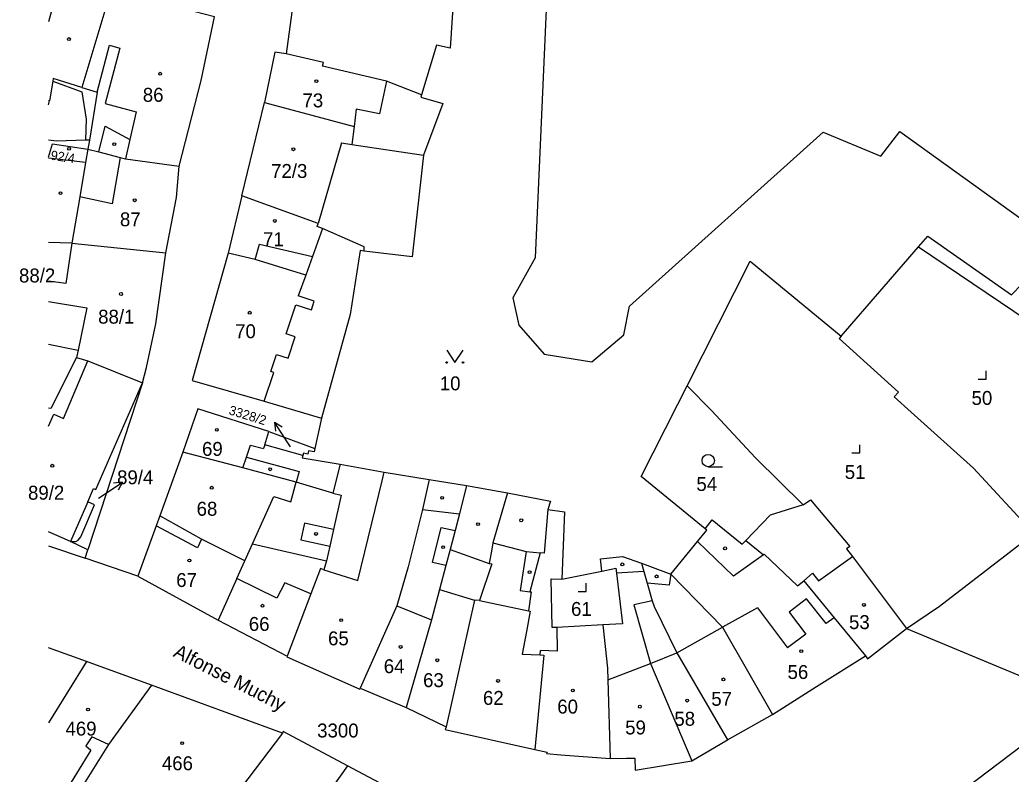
# Model space of a CAD drawing. Extents: x -600849 to -599899, y -1204328 to -1203436.
# Drawn here: x -600846.7 to -600725.7, y -1204120.9 to -1204028.8 of the extents above; entities that cross this region are included whole.
import ezdxf

# ---------------------------------------------------------------- set-up
doc = ezdxf.new("R2010")
doc.units = 0
for name, color, linetype in [('Vrstva 1', 7, 'Continuous'), ('Vrstva 2', 7, 'Continuous'), ('Vrstva 3', 7, 'Continuous'), ('Vrstva 4', 7, 'Continuous'), ('Vrstva 5', 7, 'Continuous'), ('Vrstva 7', 7, 'Continuous')]:
    doc.layers.add(name, color=color, linetype=linetype)

msp = doc.modelspace()

# ---------------------------------------------------------------- linework, layer by layer
at = {"layer": 'Vrstva 1'}
for p, q in [((-600811.67, -1204014.98), (-600814.17, -1204032.93)), ((-600835.54, -1204025.11), (-600839.12, -1204037.04)), ((-600819.57, -1204050.27), (-600816.82, -1204038.87)), ((-600838.36, -1204044.57), (-600838.64, -1204046.19)), ((-600838.64, -1204046.19), (-600843.16, -1204045.67)), ((-600819.57, -1204050.27), (-600821.24, -1204057.28)), ((-600840.32, -1204056.04), (-600841.05, -1204060.99)), ((-600840.32, -1204056.04), (-600828.84, -1204057.25)), ((-600746.41, -1204067.39), (-600736.97, -1204056.52)), ((-600843.16, -1204068.39), (-600839.53, -1204069.11)), ((-600839.53, -1204069.11), (-600839.75, -1204070.02)), ((-600831.7, -1204073.1), (-600838.37, -1204093.5)), ((-600765.22, -1204073.49), (-600762.25, -1204076.47)), ((-600809.83, -1204077.4), (-600810.67, -1204081.12)), ((-600816.28, -1204079.06), (-600810.67, -1204081.12)), ((-600826.77, -1204081.58), (-600829.59, -1204089.34)), ((-600807.55, -1204083.04), (-600808.46, -1204086.56)), ((-600796.7, -1204084.9), (-600792.16, -1204085.62)), ((-600792.16, -1204085.62), (-600787.16, -1204086.53)), ((-600782.21, -1204088.57), (-600780.17, -1204088.84)), ((-600751.07, -1204087.99), (-600755.08, -1204089.24)), ((-600780.17, -1204088.84), (-600780.52, -1204097.07)), ((-600755.08, -1204089.24), (-600758.04, -1204092.34)), ((-600758.04, -1204092.34), (-600755.91, -1204094.11)), ((-600843.16, -1204093.01), (-600838.7, -1204094.53)), ((-600838.37, -1204093.5), (-600840.47, -1204092.47)), ((-600838.7, -1204094.53), (-600838.37, -1204093.5)), ((-600832.27, -1204096.72), (-600838.7, -1204094.53)), ((-600770.8, -1204095.14), (-600767.2, -1204096.46)), ((-600832.27, -1204096.72), (-600822.47, -1204102.08)), ((-600820.17, -1204096.99), (-600822.47, -1204102.08)), ((-600780.52, -1204097.07), (-600775.64, -1204096.09)), ((-600811.15, -1204098.86), (-600814.03, -1204106.46)), ((-600784.37, -1204100.98), (-600784.83, -1204103.48)), ((-600822.47, -1204102.08), (-600814.03, -1204106.46)), ((-600775.51, -1204102.65), (-600781.14, -1204102.98)), ((-600738.45, -1204103.11), (-600717.23, -1204111.96)), ((-600838.55, -1204107.14), (-600843.16, -1204105.44)), ((-600766.49, -1204106.06), (-600760.28, -1204116.67)), ((-600838.55, -1204107.14), (-600843.16, -1204114.61)), ((-600830.6, -1204110.03), (-600838.55, -1204107.14)), ((-600769.68, -1204107.36), (-600764.65, -1204119.27)), ((-600830.6, -1204110.03), (-600835.83, -1204117.26)), ((-600814.59, -1204115.86), (-600830.6, -1204110.03)), ((-600805.11, -1204110.37), (-600799.52, -1204112.73)), ((-600799.52, -1204112.73), (-600794.63, -1204115.11)), ((-600747.51, -1204134.92), (-600717.23, -1204111.96)), ((-600760.28, -1204116.67), (-600754.81, -1204113.59)), ((-600814.59, -1204115.86), (-600823.85, -1204128.03)), ((-600764.65, -1204119.27), (-600760.28, -1204116.67)), ((-600799.24, -1204123.79), (-600806.67, -1204119.86))]:
    msp.add_line(p, q, dxfattribs=at)
for points in [[(-600781.84, -1203949), (-600781.01, -1203959.65), (-600780.83, -1203983.13), (-600781.28, -1203997.12), (-600781.6, -1204007.31), (-600784.23, -1204015.61), (-600782.99, -1204026.27), (-600782.43, -1204027.52), (-600783.78, -1204057.86), (-600786.51, -1204062.72)], [(-600793.25, -1204018.6), (-600794.15, -1204032.23), (-600795.8, -1204031.86), (-600797.64, -1204037.95)], [(-600827.23, -1204046.67), (-600824.53, -1204036.21), (-600822.91, -1204028.4), (-600835.54, -1204025.11)], [(-600814.17, -1204032.93), (-600815.56, -1204032.73), (-600816.82, -1204038.87)], [(-600797.64, -1204037.95), (-600801.93, -1204036.26), (-600809.72, -1204034.45), (-600809.61, -1204033.99), (-600814.17, -1204032.93)], [(-600839.12, -1204037.04), (-600842.61, -1204035.96), (-600842.66, -1204036.27), (-600843.06, -1204038.67), (-600843.16, -1204038.66)], [(-600839.12, -1204037.04), (-600837.23, -1204037.63), (-600838.18, -1204043.46), (-600838.36, -1204044.57)], [(-600816.82, -1204038.87), (-600805.87, -1204041.79), (-600806.13, -1204043.99), (-600797.38, -1204045.31)], [(-600797.64, -1204037.95), (-600797.72, -1204038.22), (-600795.05, -1204039), (-600797.38, -1204045.31)], [(-600786.51, -1204062.72), (-600785.78, -1204066.08), (-600782.69, -1204069.61), (-600776.86, -1204070.56), (-600772.94, -1204067.26), (-600772.25, -1204063.73), (-600748.62, -1204042.5), (-600741.59, -1204045.45), (-600739.25, -1204042.4), (-600717.66, -1204057.97), (-600709.47, -1204069.87)], [(-600843.16, -1204045.56), (-600842.69, -1204043.92), (-600838.36, -1204044.57)], [(-600838.36, -1204044.57), (-600837.03, -1204044.91), (-600834.42, -1204045.58), (-600833.78, -1204045.74), (-600827.23, -1204046.67)], [(-600838.64, -1204046.19), (-600839.34, -1204050.38), (-600840.32, -1204056.04)], [(-600797.38, -1204045.31), (-600798.79, -1204057.72), (-600804.66, -1204057.01)], [(-600828.84, -1204057.25), (-600827.56, -1204050.48), (-600827.23, -1204046.67)], [(-600809.73, -1204054.28), (-600810.38, -1204054), (-600810.27, -1204053.64), (-600819.57, -1204050.27)], [(-600809.73, -1204054.28), (-600810.96, -1204057.67), (-600811.78, -1204059.95), (-600817.93, -1204058.05), (-600821.24, -1204057.28)], [(-600804.66, -1204057.01), (-600804.63, -1204056.5), (-600809.73, -1204054.28)], [(-600840.32, -1204056.04), (-600843.16, -1204055.97)], [(-600736.97, -1204056.52), (-600735.85, -1204055.2), (-600725.62, -1204062.37), (-600724.36, -1204061.07), (-600721.14, -1204063.73), (-600719.04, -1204060.78), (-600709.47, -1204069.87)], [(-600831.7, -1204073.1), (-600831.2, -1204071.25), (-600830.06, -1204065.9), (-600828.84, -1204057.25)], [(-600821.24, -1204057.28), (-600825.65, -1204072.8), (-600816.84, -1204075.36), (-600809.83, -1204077.4)], [(-600804.66, -1204057.01), (-600805.13, -1204056.95), (-600806.34, -1204064.76), (-600809.83, -1204077.4)], [(-600736.97, -1204056.52), (-600712.07, -1204073.32), (-600705.63, -1204077.44)], [(-600765.22, -1204073.49), (-600757.51, -1204058.26), (-600746.41, -1204067.39)], [(-600841.05, -1204060.99), (-600843.16, -1204060.7)], [(-600843.16, -1204063.16), (-600838.51, -1204063.96), (-600839.53, -1204069.11)], [(-600746.41, -1204067.39), (-600746.66, -1204067.68), (-600739.43, -1204074.26), (-600739.95, -1204074.83), (-600737.87, -1204076.7)], [(-600839.75, -1204070.02), (-600842.89, -1204076.25), (-600843.16, -1204076.19)], [(-600839.75, -1204070.02), (-600838.38, -1204070.41), (-600831.7, -1204073.1)], [(-600840.47, -1204092.47), (-600839.82, -1204092.47), (-600839.54, -1204092.32), (-600839.23, -1204091.91), (-600837.55, -1204087.98), (-600838.38, -1204087.62), (-600837.68, -1204086.01), (-600837.4, -1204086.14), (-600831.7, -1204073.1)], [(-600763.02, -1204090.93), (-600770.83, -1204084.53), (-600766.38, -1204075.79), (-600765.22, -1204073.49)], [(-600816.28, -1204079.06), (-600824.94, -1204076.29), (-600826.77, -1204081.58)], [(-600762.25, -1204076.47), (-600756.88, -1204082.25), (-600751.07, -1204087.99)], [(-600737.87, -1204076.7), (-600730.26, -1204083.54), (-600722.9, -1204091.5)], [(-600812.13, -1204081.97), (-600816.77, -1204080.69), (-600816.28, -1204079.06)], [(-600810.67, -1204081.12), (-600810.76, -1204081.51), (-600811.42, -1204081.42), (-600811.5, -1204081.81), (-600812.06, -1204081.68), (-600812.13, -1204081.97)], [(-600808.46, -1204086.56), (-600812.95, -1204085.24), (-600819.47, -1204083.47), (-600826.77, -1204081.58)], [(-600812.13, -1204081.97), (-600812.21, -1204082.26), (-600807.55, -1204083.04)], [(-600807.55, -1204083.04), (-600802.2, -1204084.02), (-600796.7, -1204084.9)], [(-600796.7, -1204084.9), (-600797.54, -1204088.56), (-600799.26, -1204095.58), (-600800.66, -1204100.33), (-600805.11, -1204110.37)], [(-600792.16, -1204085.62), (-600793.01, -1204089.11), (-600793.54, -1204091.14), (-600794.15, -1204093.45), (-600794.67, -1204095.42), (-600795.44, -1204098.35), (-600796.41, -1204102.02), (-600799.52, -1204112.73)], [(-600808.46, -1204086.56), (-600807.45, -1204086.83), (-600808.39, -1204091.01), (-600808.84, -1204093.04), (-600809.23, -1204094.82), (-600809.56, -1204095.94), (-600809.97, -1204095.77), (-600811.15, -1204098.86)], [(-600787.16, -1204086.53), (-600788.93, -1204092.64), (-600789.07, -1204093.43)], [(-600787.16, -1204086.53), (-600781.89, -1204087.56), (-600782.21, -1204088.57)], [(-600751.07, -1204087.99), (-600750.18, -1204087.39), (-600745.34, -1204093.08), (-600745.77, -1204093.37), (-600745.05, -1204094.32), (-600738.45, -1204103.11)], [(-600782.21, -1204088.57), (-600782.65, -1204093.88), (-600783.17, -1204093.84), (-600784.4, -1204098.6), (-600784.27, -1204098.61), (-600784.59, -1204100.93), (-600784.37, -1204100.98)], [(-600829.59, -1204089.34), (-600830.03, -1204090.55), (-600832.27, -1204096.72)], [(-600820.17, -1204096.99), (-600819.19, -1204094.83), (-600824.48, -1204092.21), (-600829.59, -1204089.34)], [(-600763.02, -1204090.93), (-600762.16, -1204089.81), (-600758.5, -1204092.82), (-600758.04, -1204092.34)], [(-600767.2, -1204096.46), (-600763.94, -1204092.48), (-600762.81, -1204091.1), (-600763.02, -1204090.93)], [(-600840.47, -1204092.47), (-600843.16, -1204091.3)], [(-600738.45, -1204103.11), (-600734.4, -1204100.35), (-600722.9, -1204091.5)], [(-600789.07, -1204093.43), (-600789.39, -1204095.18), (-600789.04, -1204095.2), (-600790.58, -1204099.66), (-600791.18, -1204099.62), (-600794.63, -1204115.11)], [(-600775.64, -1204096.09), (-600775.81, -1204094.58), (-600773.1, -1204094.3), (-600770.8, -1204095.14)], [(-600755.91, -1204094.11), (-600755.8, -1204094.01), (-600751.73, -1204097.89), (-600750.99, -1204097.26)], [(-600775.64, -1204096.09), (-600773.93, -1204095.74), (-600773.86, -1204096.35), (-600773.11, -1204102.51), (-600775.51, -1204102.65)], [(-600770.8, -1204095.14), (-600770.5, -1204096.15), (-600770.09, -1204097.58), (-600769.47, -1204099.71)], [(-600811.15, -1204098.86), (-600814.32, -1204097.52), (-600815.28, -1204099.41), (-600820.17, -1204096.99)], [(-600781.14, -1204102.98), (-600781.69, -1204102.96), (-600781.81, -1204097.04), (-600780.52, -1204097.07)], [(-600767.2, -1204096.46), (-600760.92, -1204102.94), (-600754.81, -1204113.59)], [(-600750.99, -1204097.26), (-600747.27, -1204101.78), (-600743.44, -1204106.44)], [(-600769.47, -1204099.71), (-600771.71, -1204100.22), (-600769.68, -1204107.36)], [(-600769.47, -1204099.71), (-600769.26, -1204100.41), (-600766.49, -1204106.06)], [(-600775.51, -1204102.65), (-600774.95, -1204107.93), (-600774.91, -1204109.38), (-600774.61, -1204118.96)], [(-600743.44, -1204106.44), (-600743.2, -1204106.79), (-600738.45, -1204103.11)], [(-600784.83, -1204103.48), (-600785.34, -1204106.23), (-600783.16, -1204106.33), (-600782.71, -1204106.35), (-600783.82, -1204117.88)], [(-600814.03, -1204106.46), (-600814.06, -1204106.55), (-600805.17, -1204110.51), (-600805.11, -1204110.37)], [(-600754.81, -1204113.59), (-600749.41, -1204110.18), (-600743.44, -1204106.44)], [(-600794.63, -1204115.11), (-600794.76, -1204115.42), (-600783.82, -1204117.88)], [(-600806.67, -1204119.86), (-600814.51, -1204115.67), (-600814.59, -1204115.86)], [(-600835.83, -1204117.26), (-600838.68, -1204121.81), (-600840.92, -1204125.39)], [(-600783.82, -1204117.88), (-600782.32, -1204118.2), (-600782.38, -1204118.36), (-600780.63, -1204118.51), (-600774.61, -1204118.96)], [(-600774.61, -1204118.96), (-600772.61, -1204118.93), (-600771.6, -1204118.91), (-600771.57, -1204120.39), (-600764.65, -1204119.27)], [(-600806.67, -1204119.86), (-600812.52, -1204128.13), (-600816.88, -1204134.04), (-600819.75, -1204137.27), (-600824.52, -1204142.43), (-600829.08, -1204147.45), (-600833.81, -1204152)]]:
    msp.add_lwpolyline(points, dxfattribs=at)
at = {"layer": 'Vrstva 3'}
for p, q in [((-600728.7, -1204072.64), (-600728.7, -1204071.64)), ((-600729.7, -1204072.64), (-600728.7, -1204072.64)), ((-600744.12, -1204081.67), (-600744.12, -1204080.67)), ((-600745.12, -1204081.67), (-600744.12, -1204081.67)), ((-600762.64, -1204083.35), (-600760.89, -1204083.35)), ((-600777.53, -1204098.56), (-600777.53, -1204097.56)), ((-600778.53, -1204098.56), (-600777.53, -1204098.56))]:
    msp.add_line(p, q, dxfattribs=at)
msp.add_lwpolyline([(-600794.57, -1204069.12), (-600793.57, -1204070.62), (-600792.57, -1204069.12)], dxfattribs=at)
for centre, radius in [((-600794.57, -1204070.62), 0.1), ((-600792.57, -1204070.62), 0.1), ((-600762.64, -1204082.6), 0.75)]:
    msp.add_circle(centre, radius, dxfattribs=at)
at = {"layer": 'Vrstva 4'}
for p, q in [((-600841.6, -1204023.22), (-600843.16, -1204029.05)), ((-600837.23, -1204037.63), (-600835.72, -1204031.89)), ((-600834.48, -1204032.24), (-600836.24, -1204039)), ((-600835.72, -1204031.89), (-600834.48, -1204032.24)), ((-600842.66, -1204036.27), (-600839.1, -1204037.56)), ((-600801.93, -1204036.26), (-600802.77, -1204040.27)), ((-600839.1, -1204037.56), (-600838.58, -1204040.9)), ((-600843.16, -1204039.15), (-600843.06, -1204038.67)), ((-600836.24, -1204039), (-600832.47, -1204040.02)), ((-600832.47, -1204040.02), (-600833.24, -1204043.4)), ((-600805.61, -1204039.68), (-600805.87, -1204041.79)), ((-600802.77, -1204040.27), (-600805.61, -1204039.68)), ((-600838.58, -1204040.9), (-600838.67, -1204043.48)), ((-600837.03, -1204044.91), (-600836.26, -1204041.76)), ((-600836.26, -1204041.76), (-600833.24, -1204043.4)), ((-600842.18, -1204043.61), (-600843.16, -1204043.47)), ((-600838.67, -1204043.48), (-600842.18, -1204043.61)), ((-600838.18, -1204043.46), (-600838.67, -1204043.48)), ((-600833.24, -1204043.4), (-600833.78, -1204045.74)), ((-600807.39, -1204043.8), (-600810.27, -1204053.64)), ((-600807.39, -1204043.8), (-600806.13, -1204043.99)), ((-600834.42, -1204045.58), (-600835.39, -1204051.25)), ((-600835.39, -1204051.25), (-600839.34, -1204050.38)), ((-600817.93, -1204058.05), (-600817.4, -1204056.18)), ((-600817.4, -1204056.18), (-600810.96, -1204057.67)), ((-600811.78, -1204059.95), (-600812.7, -1204062.5)), ((-600810.74, -1204063.13), (-600812.7, -1204062.5)), ((-600811.08, -1204064.19), (-600810.74, -1204063.13)), ((-600814.17, -1204067.13), (-600812.98, -1204063.57)), ((-600812.98, -1204063.57), (-600811.08, -1204064.19)), ((-600813.05, -1204067.5), (-600814.17, -1204067.13)), ((-600813.92, -1204070.1), (-600813.05, -1204067.5)), ((-600841.35, -1204077.46), (-600838.38, -1204070.41)), ((-600816.04, -1204071.73), (-600815.34, -1204069.63)), ((-600815.34, -1204069.63), (-600813.92, -1204070.1)), ((-600815.67, -1204071.85), (-600816.04, -1204071.73)), ((-600816.84, -1204075.36), (-600815.67, -1204071.85)), ((-600843.16, -1204078.38), (-600842.51, -1204076.94)), ((-600842.51, -1204076.94), (-600841.35, -1204077.46)), ((-600819.01, -1204082.16), (-600818.51, -1204080.73)), ((-600818.51, -1204080.73), (-600816.91, -1204081.14)), ((-600816.77, -1204080.69), (-600816.91, -1204081.14)), ((-600819.47, -1204083.47), (-600819.01, -1204082.16)), ((-600819.01, -1204082.16), (-600812.58, -1204083.94)), ((-600812.58, -1204083.94), (-600812.95, -1204085.24)), ((-600805.43, -1204097.23), (-600802.45, -1204085.08)), ((-600802.45, -1204085.08), (-600802.2, -1204084.02)), ((-600813.6, -1204087.64), (-600812.95, -1204085.24)), ((-600818.26, -1204092.77), (-600815.66, -1204086.99)), ((-600815.66, -1204086.99), (-600813.6, -1204087.64)), ((-600838.38, -1204087.62), (-600840.47, -1204092.47)), ((-600797.54, -1204088.56), (-600793.01, -1204089.11)), ((-600825, -1204093.24), (-600830.03, -1204090.55)), ((-600811.91, -1204090.22), (-600812.36, -1204092.26)), ((-600808.39, -1204091.01), (-600811.91, -1204090.22)), ((-600796.29, -1204095.04), (-600795.24, -1204090.76)), ((-600795.24, -1204090.76), (-600793.54, -1204091.14)), ((-600824.48, -1204092.21), (-600825, -1204093.24)), ((-600812.36, -1204092.26), (-600808.84, -1204093.04)), ((-600819.19, -1204094.83), (-600818.26, -1204092.77)), ((-600818.26, -1204092.77), (-600809.23, -1204094.82)), ((-600794.15, -1204093.45), (-600789.39, -1204095.18)), ((-600788.93, -1204092.64), (-600784.88, -1204093.71)), ((-600763.94, -1204092.48), (-600759.54, -1204096.71)), ((-600784.88, -1204093.71), (-600785.6, -1204098.47)), ((-600784.88, -1204093.71), (-600783.17, -1204093.84)), ((-600755.91, -1204094.11), (-600759.54, -1204096.71)), ((-600749.18, -1204097.26), (-600745.05, -1204094.32)), ((-600809.56, -1204095.94), (-600805.43, -1204097.23)), ((-600794.67, -1204095.42), (-600796.29, -1204095.04)), ((-600770.5, -1204096.15), (-600773.86, -1204096.35)), ((-600767.2, -1204096.46), (-600767.42, -1204097.79)), ((-600750.99, -1204097.26), (-600749.92, -1204096.35)), ((-600749.92, -1204096.35), (-600749.18, -1204097.26)), ((-600795.44, -1204098.35), (-600791.18, -1204099.62)), ((-600767.42, -1204097.79), (-600770.09, -1204097.58)), ((-600785.6, -1204098.47), (-600784.4, -1204098.6)), ((-600750.64, -1204099.48), (-600752.75, -1204101.1)), ((-600748.24, -1204102.49), (-600750.64, -1204099.48)), ((-600800.66, -1204100.33), (-600796.41, -1204102.02)), ((-600790.58, -1204099.66), (-600784.59, -1204100.93)), ((-600756.63, -1204100.59), (-600760.92, -1204102.94)), ((-600756.63, -1204100.59), (-600752.96, -1204105.46)), ((-600752.75, -1204101.1), (-600750.73, -1204103.8)), ((-600747.27, -1204101.78), (-600748.24, -1204102.49)), ((-600781.14, -1204102.98), (-600781.07, -1204105.88)), ((-600766.49, -1204106.06), (-600760.92, -1204102.94)), ((-600750.73, -1204103.8), (-600752.96, -1204105.46)), ((-600783.16, -1204106.33), (-600783.12, -1204105.78)), ((-600781.07, -1204105.88), (-600783.12, -1204105.78)), ((-600769.68, -1204107.36), (-600766.49, -1204106.06)), ((-600774.91, -1204109.38), (-600769.68, -1204107.36)), ((-600837.88, -1204116.33), (-600838.61, -1204117.43)), ((-600835.83, -1204117.26), (-600837.88, -1204116.33)), ((-600838.61, -1204117.43), (-600837.99, -1204117.94)), ((-600837.99, -1204117.94), (-600842.55, -1204125.3))]:
    msp.add_line(p, q, dxfattribs=at)
at = {"layer": 'Vrstva 5'}
for centre in [(-600840.67, -1204031.13), (-600829.54, -1204035.37), (-600810.47, -1204036.27), (-600835.14, -1204043.96), (-600840.66, -1204044.53), (-600813.28, -1204044.59), (-600841.71, -1204049.95), (-600832.65, -1204050.82), (-600815.55, -1204053.34), (-600834.32, -1204062.26), (-600818.61, -1204064.54), (-600822.62, -1204078.85), (-600842.71, -1204083.22), (-600816.11, -1204083.66), (-600823.25, -1204085.91), (-600795.12, -1204087.15), (-600785.46, -1204089.89), (-600790.74, -1204090.36), (-600810.51, -1204091.55), (-600794.99, -1204093.17), (-600760.59, -1204093.31), (-600825.98, -1204094.79), (-600773.13, -1204095.27), (-600784.45, -1204096.22), (-600768.95, -1204096.73), (-600817.05, -1204100.32), (-600743.64, -1204100.22), (-600807.44, -1204102.08), (-600800.19, -1204105.35), (-600795.72, -1204106.98), (-600751.29, -1204105.87), (-600760.79, -1204109.31), (-600788.3, -1204109.5), (-600779.17, -1204110.67), (-600765.22, -1204111.9), (-600838.34, -1204112.98), (-600771, -1204112.64), (-600826.85, -1204117.1)]:
    msp.add_circle(centre, 0.175, dxfattribs=at)
at = {"layer": 'Vrstva 7'}
for p, q in [((-600813.97, -1204080.41), (-600815.6, -1204077.89)), ((-600815.6, -1204077.89), (-600814.64, -1204078.46)), ((-600815.6, -1204077.89), (-600815.48, -1204079.01)), ((-600813.65, -1204080.91), (-600813.97, -1204080.41)), ((-600836.62, -1204086.9), (-600834.13, -1204085.22)), ((-600834.13, -1204085.22), (-600835.24, -1204085.37)), ((-600834.13, -1204085.22), (-600834.68, -1204086.2)), ((-600837.08, -1204087.2), (-600836.62, -1204086.9))]:
    msp.add_line(p, q, dxfattribs=at)

# ---------------------------------------------------------------- texts
at = {"layer": 'Vrstva 2'}
for s, p in [('86', (-600831.66, -1204038.79)), ('73', (-600812.17, -1204039.47)), ('72/3', (-600816, -1204048.09)), ('87', (-600834.45, -1204053.99)), ('71', (-600816.98, -1204056.42)), ('88/2', (-600846.77, -1204060.85)), ('88/1', (-600837.11, -1204065.88)), ('70', (-600820.39, -1204067.66)), ('10', (-600795.41, -1204074.02)), ('50', (-600730.5, -1204075.8)), ('69', (-600824.43, -1204082.02)), ('89/4', (-600834.8, -1204085.49)), ('51', (-600745.98, -1204084.84)), ('54', (-600764.09, -1204086.3)), ('89/2', (-600845.67, -1204087.37)), ('68', (-600825.09, -1204089.33)), ('67', (-600827.58, -1204098.03)), ('61', (-600779.39, -1204101.56)), ('66', (-600818.72, -1204103.39)), ('53', (-600745.46, -1204103.17)), ('65', (-600809.05, -1204105.15)), ('64', (-600802.25, -1204108.55)), ('56', (-600752.96, -1204109.26)), ('63', (-600797.45, -1204110.25)), ('62', (-600790.14, -1204112.42)), ('57', (-600762.27, -1204112.53)), ('60', (-600781.07, -1204113.48)), ('58', (-600766.78, -1204114.97)), ('469', (-600841.1, -1204116.17)), ('3300', (-600810.38, -1204116.4)), ('59', (-600772.78, -1204116.03)), ('466', (-600829.33, -1204120.4))]:
    msp.add_text(s, height=1.7, dxfattribs=at).set_placement(p)
for s, height, rotation, p in [('92/4', 1.139, 351, (-600842.97, -1204045.84)), ('3328/2', 1.14, 343, (-600821.25, -1204076.92))]:
    msp.add_text(s, height=height, rotation=rotation, dxfattribs=at).set_placement(p)
at = {"layer": 'Vrstva 7'}
msp.add_text('Alfonse Muchy', height=1.7, rotation=333, dxfattribs=at).set_placement((-600828.06, -1204106.46))

doc.saveas('drawing.dxf')
